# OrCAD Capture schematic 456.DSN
size A4; title: OPEN CV 甫 捞侩茄 胶付飘 荣眉绢
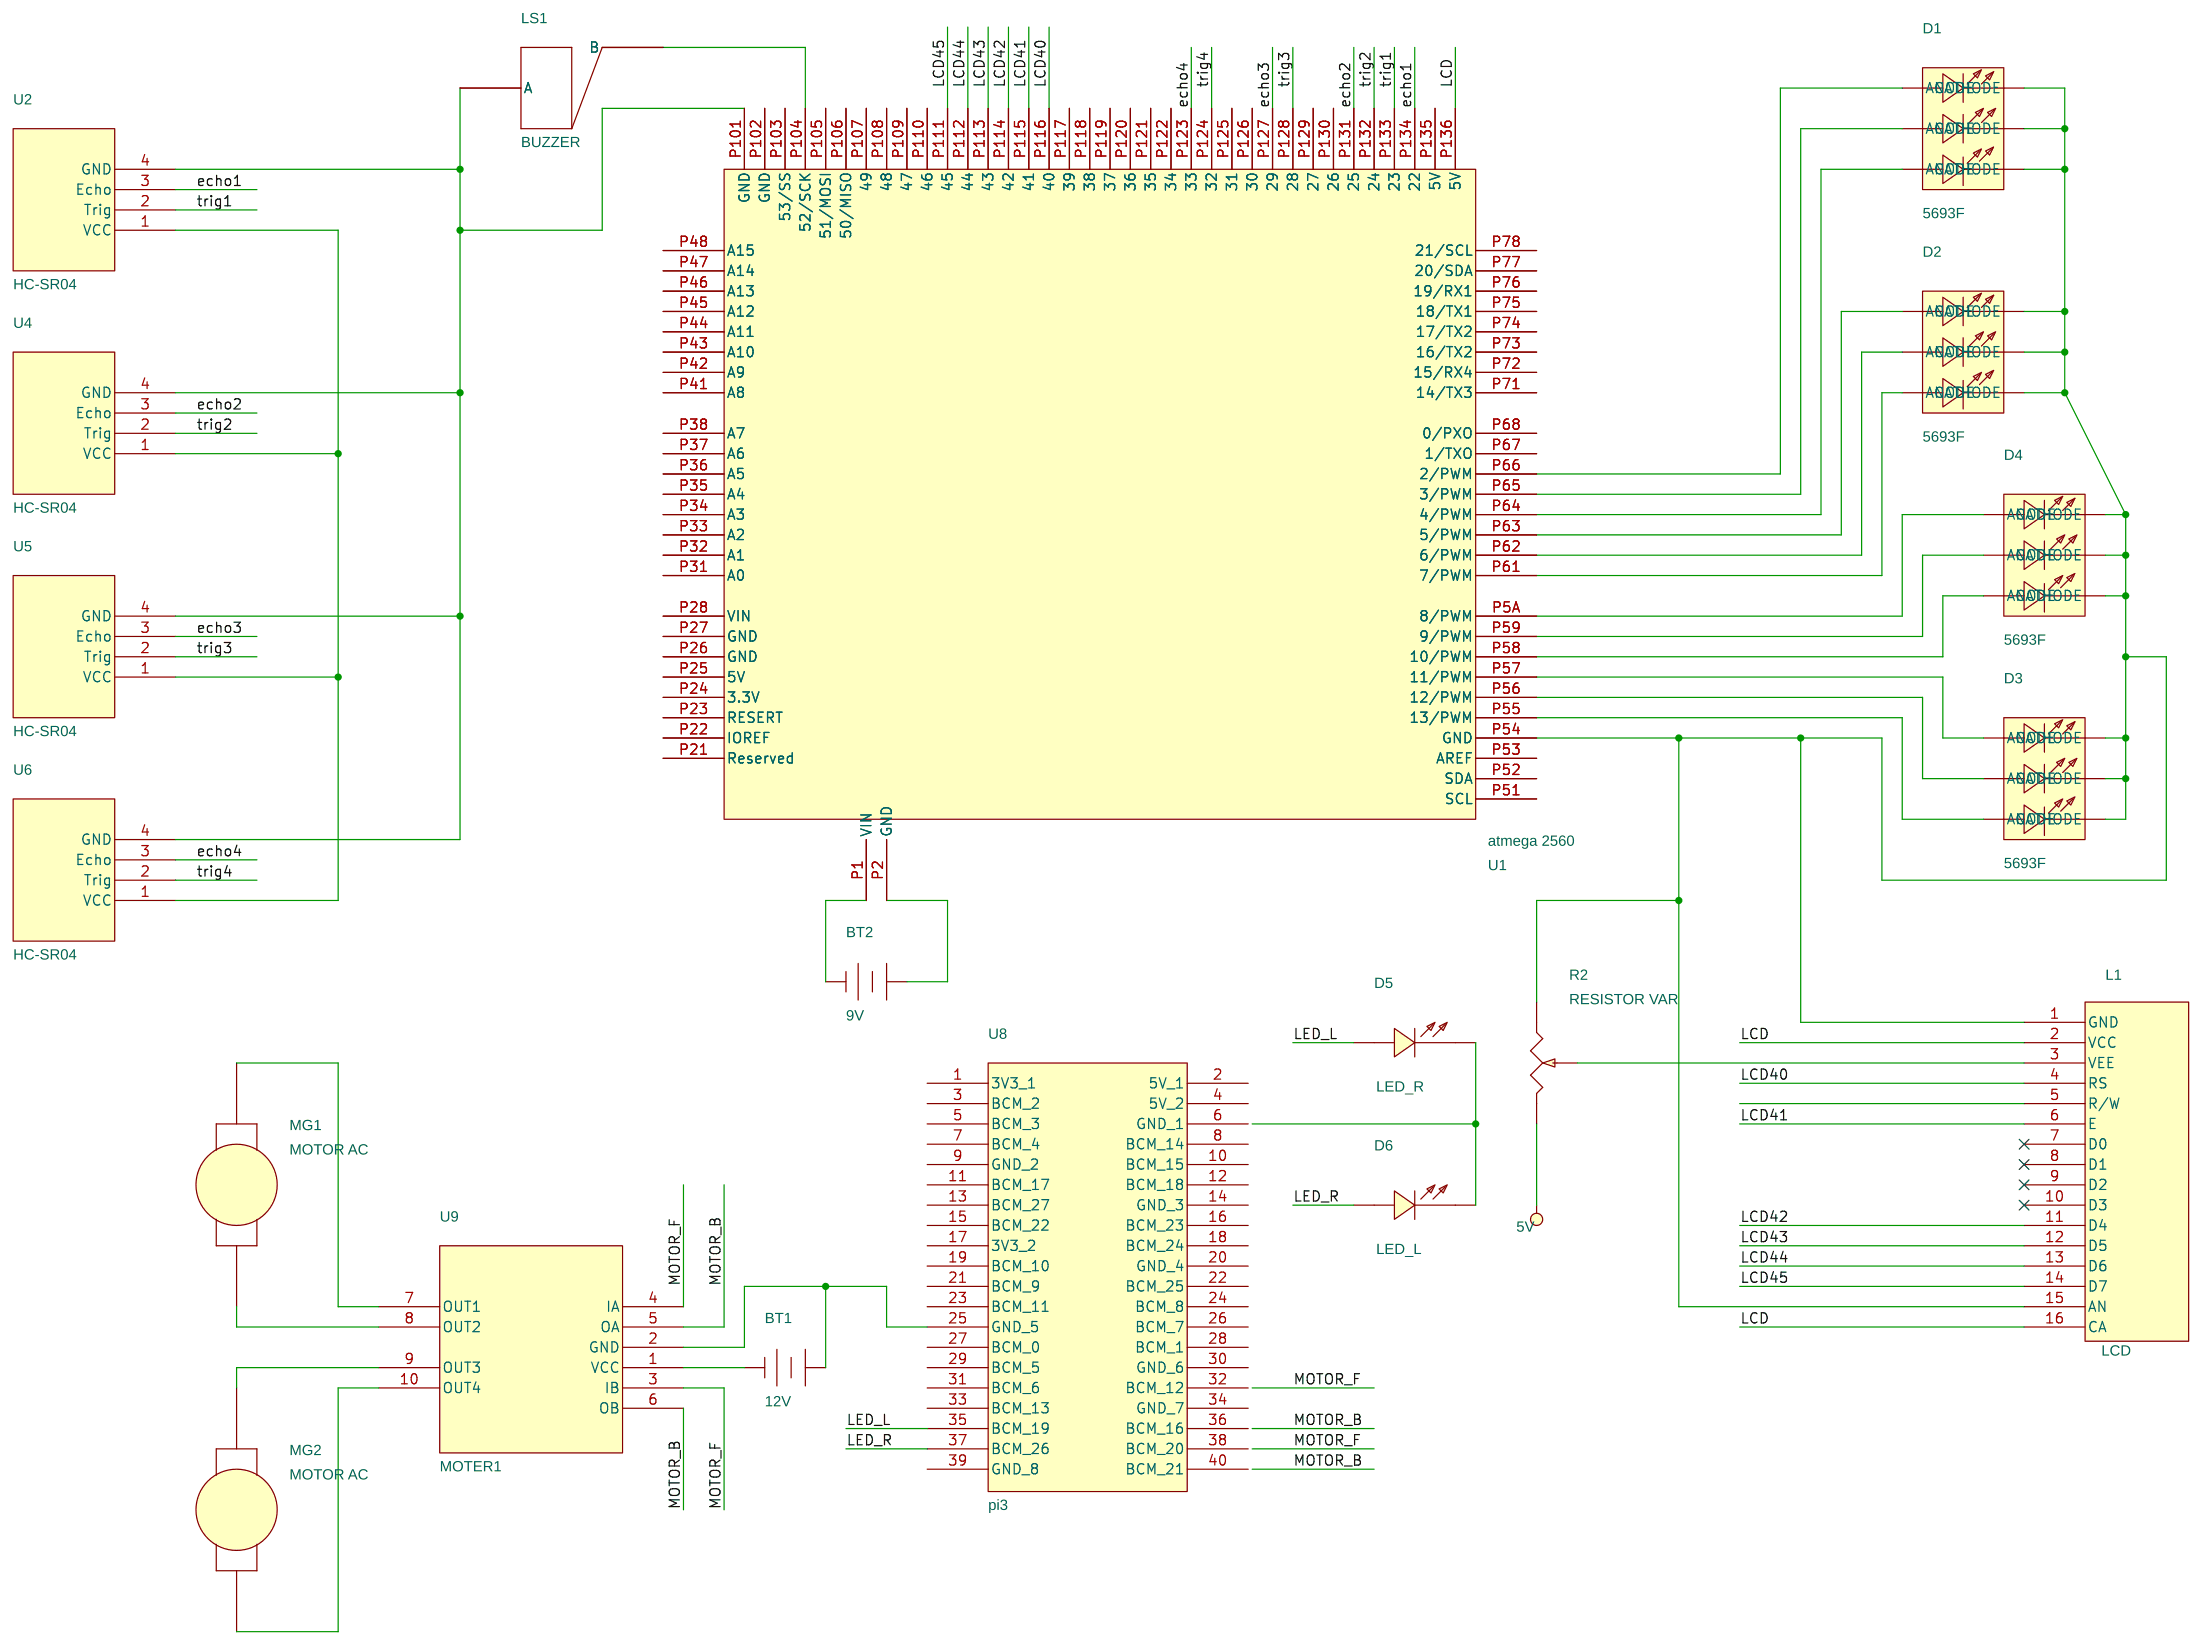
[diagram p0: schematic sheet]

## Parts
BT1  12V
BT2  9V
D1  5693F
D2  5693F
D3  5693F
D4  5693F
D5  LED_R
D6  LED_L
L1  LCD
LS1  BUZZER
MG1  MOTOR AC
MG2  MOTOR AC
R2  RESISTOR VAR
U1  atmega 2560
U2  HC-SR04
U4  HC-SR04
U5  HC-SR04
U6  HC-SR04
U8  pi3
U9  MOTER1

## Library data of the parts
BT1 BT2 = BATTERY
D1-D4 = 5693F
D5 D6 = LED
L1 = LCD_1
LS1 = BUZZER
MG1 MG2 = MOTOR_AC
R2 = RESISTOR_VAR
U1 = atmega_2560_1
U2 U4-U6 = HC-SR04
U8 = pi3_0
U9 = MOTER1_2

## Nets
3.3V: U1.P24(3.3V)
3V3_1: U8.1(3V3)
3V3_2: U8.17(3V3_2)
5V: R2.3(B) U1.P25(5V)
5V_1: U8.2(5V_1)
5V_2: U8.4(5V_2)
GND: U1.P26(GND) U1.P27(GND)
GND_1: U8.6(GND_1)
GND_2: U8.9(GND_2)
GND_3: U8.14(GND_3)
GND_4: U8.20(GND_4)
GND_6: U8.30(GND_6)
GND_7: U8.34(GND_7)
echo1: U1.P134(22) U2.3(Echo)
echo2: U1.P131(25) U4.3(Echo)
echo3: U1.P127(29) U5.3(Echo)
echo4: U1.P123(33) U6.3(Echo)
LCD: L1.2(VCC) L1.16(CA) U1.P136(5V)
LCD40: L1.4(RS) U1.P116(40)
LCD41: L1.6(E) U1.P115(41)
LCD42: L1.11(D4) U1.P114(42)
LCD43: L1.12(D5) U1.P113(43)
LCD44: L1.13(D6) U1.P112(44)
LCD45: L1.14(D7) U1.P111(45)
LED_L: D5.2(ANODE) U8.35(BCM_19)
LED_R: D6.2(ANODE) U8.37(BCM_26)
MOTOR_B: U9.5(OA) U9.6(OB)
MOTOR_F: U9.3(IB) U9.4(IA)
trig1: U1.P133(23) U2.2(Trig)
trig2: U1.P132(24) U4.2(Trig)
trig3: U1.P128(28) U5.2(Trig)
trig4: U1.P124(32) U6.2(Trig)
N02454: LS1.1(A) U1.P101(GND) U2.4(GND) U4.4(GND) U5.4(GND) U6.4(GND)
N02518: U2.1(VCC) U4.1(VCC) U5.1(VCC) U6.1(VCC)
N03724: D1.2(CATHODE) D1.4(CATHODE) D1.6(CATHODE) D2.2(CATHODE) D2.4(CATHODE) D2.6(CATHODE) D3.2(CATHODE) D3.4(CATHODE) D3.6(CATHODE) D4.2(CATHODE) D4.4(CATHODE) D4.6(CATHODE) L1.1(GND) L1.15(AN) R2.1(A) U1.P54(GND)
N04755: L1.3(VEE) R2.2(WIPER)
N05070: MG1.1 U9.8(OUT2)
N05079: MG1.2 U9.7(OUT1)
N05096: MG2.2 U9.9(OUT3)
N05449: BT1.2(-) U9.1(VCC)
N05453: BT1.1(+) U8.25(GND_5) U9.2(GND)
N05833: D5.1(CATHODE) D6.1(CATHODE)
N08158: D1.1(ANODE) U1.P66(2/PWM)
N08170: D1.3(ANODE) U1.P65(3/PWM)
N08182: D1.5(ANODE) U1.P64(4/PWM)
N08194: D2.1(ANODE) U1.P63(5/PWM)
N08206: D2.3(ANODE) U1.P62(6/PWM)
N08218: D2.5(ANODE) U1.P61(7/PWM)
N08452: D4.1(ANODE) U1.P5A(8/PWM)
N08464: D4.3(ANODE) U1.P59(9/PWM)
N08476: D4.5(ANODE) U1.P58(10/PWM)
N08491: D3.1(ANODE) U1.P57(11/PWM)
N08503: D3.3(ANODE) U1.P56(12/PWM)
N08518: D3.5(ANODE) U1.P55(13/PWM)
N08758: BT2.1(+) U1.P2(GND)
N08771: BT2.2(-) U1.P1(VIN)
N09315: LS1.2(B) U1.P104(52/SCK)
N10848: MG2.1 U9.10(OUT4)

Not connected (* = marked no-connect by the designer): L1 5(R/W) 7(D0)* 8(D1)* 9(D2)* 10(D3)*; U1 P21(Reserved) P22(IOREF) P23(RESERT) P28(VIN) P31(A0) P32(A1) P33(A2) P34(A3) P35(A4) P36(A5) P37(A6) P38(A7) P41(A8) P42(A9) P43(A10) P44(A11) P45(A12) P46(A13) P47(A14) P48(A15) P51(SCL) P52(SDA) P53(AREF) P67(1/TXO) P68(0/PXO) P71(14/TX3) P72(15/RX4) P73(16/TX2) P74(17/TX2) P75(18/TX1) P76(19/RX1) P77(20/SDA) P78(21/SCL) P102(GND) P103(53/SS) P105(51/MOSI) P106(50/MISO) P107(49) P108(48) P109(47) P110(46) P117(39) P118(38) P119(37) P120(36) P121(35) P122(34) P125(31) P126(30) P129(27) P130(26) P135(5V); U8 3(BCM_2) 5(BCM_3) 7(BCM_4) 8(BCM_14) 10(BCM_15) 11(BCM_17) 12(BCM_18) 13(BCM_27) 15(BCM_22) 16(BCM_23) 18(BCM_24) 19(BCM_10) 21(BCM_9) 22(BCM_25) 23(BCM_11) 24(BCM_8) 26(BCM_7) 27(BCM_0) 28(BCM_1) 29(BCM_5) 31(BCM_6) 32(BCM_12) 33(BCM_13) 36(BCM_16) 38(BCM_20) 39(GND_8) 40(BCM_21)
